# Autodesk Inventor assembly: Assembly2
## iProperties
Shininess: 64.0
Length Units: 11269
Angle Units: 11279
Time Units: 11290
Mass Units: 11283
Length Display Precision: 3
Angle Display Precision: 2
Created: 2002-01
Part Number: Assembly2
Document SubType Name: Assembly
Designer: ***
Density: 0.0
Volumn: 0.0
Area: 0.0
PropertySet Name: Model Information
Control State: 0
Master: False
Checked Out: False
Author: ***
